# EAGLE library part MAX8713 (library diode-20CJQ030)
Maxim's MAX8713 Simplified Multichemistry SMBus Battery Charger Description: The MAX8713 multichemistry battery charger simplifies construction of smart chargers with a minimum number of external components. It uses the Intel System Management Bus (SMBus?) to control the charge voltage and charge current. High efficiency is achieved through the use of a constant off-time step-down topology with synchronous rectification. The MAX8713 charges one to four lithium-ion (Li+) cells in series and delivers over 2A charge current?scalable with the sense resistor. The MAX8713 drives n-channel MOSFETs for improved efficiency and reduced cost. A low-offset charge-current-sense amplifier provides highaccuracy charge current with small sense resistors. The MAX8713 is available in a space-saving 24-pin 4mm x 4mm thin QFN package and operates over the extended (-40°C to +85°C) temperature range. An evaluation kit is available to reduce design time. Features: Over 2A Charge Current Intel SMBus 2-Wire Serial Interface ±0.6% Charge Voltage Accuracy 11-Bit Charge Voltage Resolution 6-Bit Charge Current Resolution Adjustable Switching Frequency +8V to +28V Input Voltage Range Cycle-By-Cycle Current Limit Charges Any Battery Chemistry (Li+, NiCd, NiMH,Lead Acid, etc.) Small 24-Pin TQFN Applications: Handset Car Kits Digital Cameras PDAs and Tablet Computers Notebook Computers Portable Equipment with Rechargeable Batteries Please send any comments to: messi@users.sourceforge.net
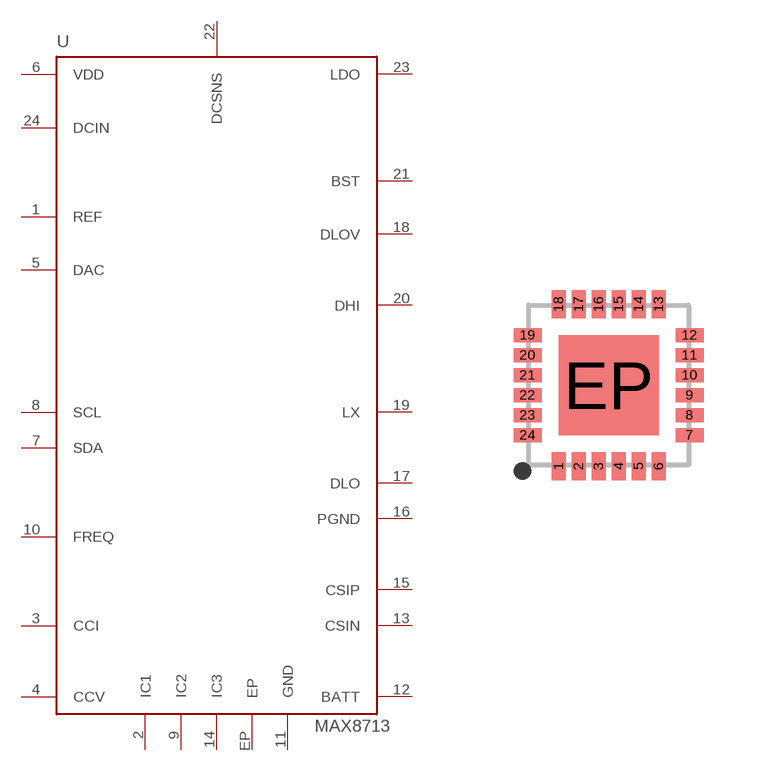
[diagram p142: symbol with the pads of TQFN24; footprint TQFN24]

Designator prefix U

## MAX8713  [TQFN24]
1  REF  out
2  IC1  pas
3  CCI  in
4  CCV  in
5  DAC  out
6  VDD  pwr
7  SDA
8  SCL  in
9  IC2  pas
10  FREQ  in
11  GND  pwr
12  BATT  in
13  CSIN  in
14  IC3  pas
15  CSIP  in
16  PGND  pwr
17  DLO  out
18  DLOV  in
19  LX  in
20  DHI  out
21  BST  out
22  DCSNS  in
23  LDO  out
24  DCIN  pwr
EP  EP  pas

## Footprint TQFN24 (pad centres in mm)
Maxim's Package TQFN24 e.g. MAX8713
smd 0.35 x 0.7: 1 -1.25,-2.025; 2 -0.75,-2.025; 3 -0.25,-2.025; 4 0.25,-2.025; 5 0.75,-2.025; 6 1.25,-2.025; 13 1.25,2.025; 14 0.75,2.025; 15 0.25,2.025; 16 -0.25,2.025; 17 -0.75,2.025; 18 -1.25,2.025
smd 0.7 x 0.35: 7 2.025,-1.25; 8 2.025,-0.75; 9 2.025,-0.25; 10 2.025,0.25; 11 2.025,0.75; 12 2.025,1.25; 19 -2.025,1.25; 20 -2.025,0.75; 21 -2.025,0.25; 22 -2.025,-0.25; 23 -2.025,-0.75; 24 -2.025,-1.25
smd 2.5 x 2.5: EP 0,0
